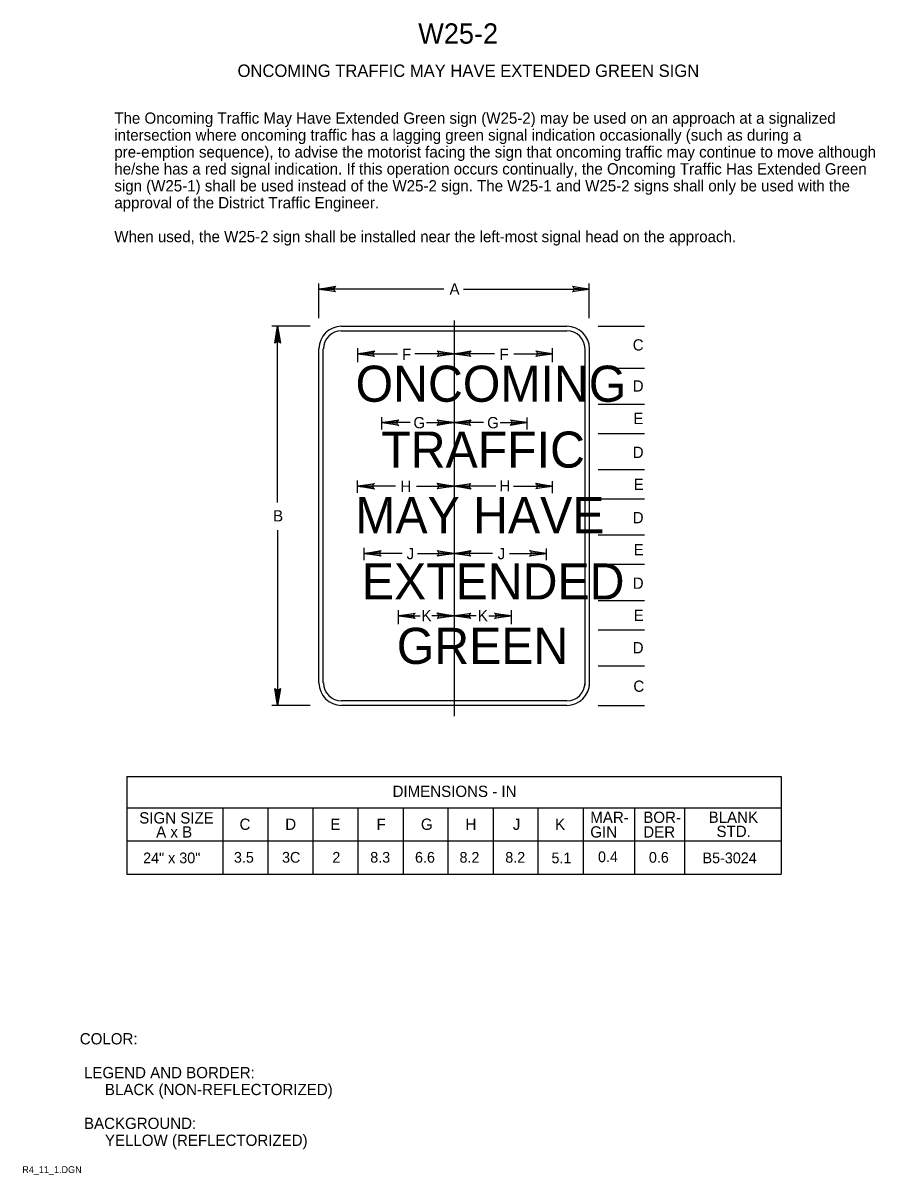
# Model space of a CAD drawing. Extents: x 0.013 to 0.201, y 0.004 to 0.259.
import ezdxf

# ---------------------------------------------------------------- set-up
doc = ezdxf.new("R2010")
doc.units = 0
for name, color, linetype in [('1', 7, 'Continuous'), ('11', 7, 'Continuous'), ('12', 7, 'Continuous'), ('2', 7, 'Continuous'), ('3', 7, 'Continuous')]:
    doc.layers.add(name, color=color, linetype=linetype)

# ---------------------------------------------------------------- blocks, each defined once
blk = doc.blocks.new('RARROW')
at = {"layer": '3'}
for p, q in [((-2.156, 0.285), (-2.2665, 0.384625)), ((-2.2665, 0.384625), (0, 0)), ((0, 0), (-2.2665, -0.379125)), ((-2.156, 0.285), (-2.075625, 0.12075)), ((0, 0), (-2.156, 0.285)), ((-2.14975, -0.2705), (0, 0)), ((-2.075625, 0.12075), (0, 0)), ((0, 0), (-2.074, -0.108)), ((-2.2665, -0.379125), (-2.14975, -0.2705)), ((-2.074, -0.108), (-2.14975, -0.2705))]:
    blk.add_line(p, q, dxfattribs=at)

msp = doc.modelspace()

# ---------------------------------------------------------------- linework, layer by layer
at = {"layer": '11'}
for p, q in [((0.08313, 0.192), (0.13312, 0.192)), ((0.07812, 0.113), (0.07812, 0.187)), ((0.13812, 0.187), (0.13812, 0.11235)), ((0.13312, 0.108), (0.08313, 0.108))]:
    msp.add_line(p, q, dxfattribs=at)
for centre, start, end in [((0.08317, 0.18699), 90, 180), ((0.13317, 0.18699), 0, 90), ((0.08317, 0.113), 180, 270), ((0.13317, 0.113), 270, 0)]:
    msp.add_arc(centre, 0.005, start, end, dxfattribs=at)
at = {"layer": '3'}
for p, q in [((0.07812, 0.19376), (0.07812, 0.2015)), ((0.10587, 0.20025), (0.07812, 0.20025)), ((0.11025, 0.20025), (0.13812, 0.20025)), ((0.13812, 0.19376), (0.13812, 0.2015)), ((0.07625, 0.192), (0.06775, 0.192)), ((0.069, 0.15293), (0.069, 0.192)), ((0.10812, 0.19325), (0.10812, 0.10562)), ((0.14012, 0.192), (0.15038, 0.192)), ((0.08313, 0.191), (0.13312, 0.191)), ((0.07912, 0.113), (0.07912, 0.187)), ((0.08676, 0.18405), (0.08676, 0.18716)), ((0.10812, 0.18729), (0.10812, 0.18466)), ((0.10812, 0.18591), (0.11188, 0.18653)), ((0.11168, 0.18635), (0.10812, 0.18591)), ((0.11156, 0.18609), (0.11168, 0.18635)), ((0.11188, 0.18653), (0.11168, 0.18635)), ((0.12642, 0.18638), (0.12624, 0.18654)), ((0.12624, 0.18654), (0.12999, 0.18591)), ((0.12642, 0.18638), (0.12656, 0.18611)), ((0.12999, 0.18591), (0.12642, 0.18638)), ((0.12999, 0.18405), (0.12999, 0.18716)), ((0.13712, 0.187), (0.13712, 0.11242)), ((0.08681, 0.18591), (0.09557, 0.18591)), ((0.10877, 0.18591), (0.09946, 0.18591)), ((0.10812, 0.18591), (0.11156, 0.18609)), ((0.11313, 0.18591), (0.10812, 0.18591)), ((0.11156, 0.18571), (0.10812, 0.18591)), ((0.10812, 0.18591), (0.11169, 0.18544)), ((0.11188, 0.18528), (0.10812, 0.18591)), ((0.11712, 0.18591), (0.10812, 0.18591)), ((0.11169, 0.18544), (0.11156, 0.18571)), ((0.11169, 0.18544), (0.11188, 0.18528)), ((0.12136, 0.18591), (0.12999, 0.18591)), ((0.12999, 0.18591), (0.12624, 0.18529)), ((0.12624, 0.18529), (0.12643, 0.18547)), ((0.12643, 0.18547), (0.12999, 0.18591)), ((0.12656, 0.18573), (0.12643, 0.18547)), ((0.12656, 0.18611), (0.12999, 0.18591)), ((0.12999, 0.18591), (0.12656, 0.18573)), ((0.14012, 0.18275), (0.15038, 0.18275)), ((0.14012, 0.17475), (0.15038, 0.17475)), ((0.0921, 0.16914), (0.0921, 0.17189)), ((0.10812, 0.17264), (0.10812, 0.16939)), ((0.12437, 0.16912), (0.12437, 0.17175)), ((0.0984, 0.17064), (0.09253, 0.17064)), ((0.10201, 0.17064), (0.10812, 0.17064)), ((0.11467, 0.17064), (0.10867, 0.17064)), ((0.11837, 0.17064), (0.12418, 0.17064)), ((0.14012, 0.16825), (0.15038, 0.16825)), ((0.14012, 0.16025), (0.15038, 0.16025)), ((0.08672, 0.15507), (0.08672, 0.15782)), ((0.09514, 0.15657), (0.08715, 0.15657)), ((0.09978, 0.15657), (0.10812, 0.15657)), ((0.10812, 0.15745), (0.10812, 0.15482)), ((0.11741, 0.15657), (0.10892, 0.15657)), ((0.12133, 0.15657), (0.12979, 0.15657)), ((0.12998, 0.15505), (0.12998, 0.15768)), ((0.14012, 0.15375), (0.15038, 0.15375)), ((0.069, 0.14685), (0.069, 0.108)), ((0.14012, 0.14575), (0.15038, 0.14575)), ((0.10812, 0.14362), (0.10812, 0.14037)), ((0.08822, 0.14018), (0.08822, 0.14293)), ((0.09664, 0.14168), (0.08865, 0.14168)), ((0.10003, 0.14168), (0.10812, 0.14168)), ((0.11665, 0.14168), (0.10867, 0.14168)), ((0.12039, 0.14168), (0.12842, 0.14168)), ((0.12861, 0.14016), (0.12861, 0.14278)), ((0.14012, 0.13925), (0.15038, 0.13925)), ((0.14012, 0.13125), (0.15038, 0.13125)), ((0.09579, 0.12597), (0.09579, 0.12909)), ((0.09579, 0.12784), (0.10059, 0.12784)), ((0.10877, 0.12784), (0.10318, 0.12784)), ((0.10812, 0.12921), (0.10812, 0.12659)), ((0.10812, 0.12784), (0.11188, 0.12846)), ((0.11168, 0.12828), (0.10812, 0.12784)), ((0.10812, 0.12784), (0.11156, 0.12801)), ((0.11156, 0.12764), (0.10812, 0.12784)), ((0.10812, 0.12784), (0.11169, 0.12737)), ((0.11188, 0.12721), (0.10812, 0.12784)), ((0.11279, 0.12784), (0.10812, 0.12784)), ((0.11307, 0.12784), (0.10812, 0.12784)), ((0.11156, 0.12801), (0.11168, 0.12828)), ((0.11169, 0.12737), (0.11156, 0.12764)), ((0.11188, 0.12846), (0.11168, 0.12828)), ((0.11586, 0.12784), (0.12085, 0.12784)), ((0.11729, 0.1283), (0.1171, 0.12846)), ((0.1171, 0.12846), (0.12085, 0.12784)), ((0.12085, 0.12784), (0.1171, 0.12721)), ((0.11729, 0.1283), (0.11742, 0.12803)), ((0.12085, 0.12784), (0.11729, 0.1283)), ((0.1173, 0.12739), (0.12085, 0.12784)), ((0.11742, 0.12766), (0.1173, 0.12739)), ((0.11742, 0.12803), (0.12085, 0.12784)), ((0.12085, 0.12784), (0.11742, 0.12766)), ((0.12085, 0.12597), (0.12085, 0.12909)), ((0.11169, 0.12737), (0.11188, 0.12721)), ((0.1171, 0.12721), (0.1173, 0.12739)), ((0.14012, 0.12475), (0.15038, 0.12475)), ((0.14012, 0.11675), (0.15038, 0.11675)), ((0.07625, 0.108), (0.06775, 0.108)), ((0.13312, 0.109), (0.08313, 0.109)), ((0.14012, 0.108), (0.15038, 0.108)), ((0.03556, 0.0922), (0.03556, 0.07057)), ((0.03556, 0.0922), (0.18069, 0.0922)), ((0.18069, 0.0922), (0.18069, 0.07057)), ((0.03556, 0.08532), (0.15671, 0.08532)), ((0.05686, 0.08532), (0.05686, 0.07057)), ((0.06681, 0.08532), (0.06681, 0.07057)), ((0.07681, 0.08532), (0.07681, 0.07057)), ((0.08681, 0.08532), (0.08681, 0.07057)), ((0.09681, 0.08532), (0.09681, 0.07057)), ((0.10677, 0.08532), (0.10677, 0.07057)), ((0.1168, 0.08532), (0.1168, 0.07057)), ((0.12672, 0.08532), (0.12672, 0.07057)), ((0.13676, 0.08532), (0.13676, 0.07057)), ((0.14814, 0.08532), (0.14814, 0.07057)), ((0.15671, 0.08532), (0.18069, 0.08532)), ((0.15926, 0.08532), (0.15926, 0.07057)), ((0.03556, 0.07795), (0.15671, 0.07795)), ((0.15671, 0.07795), (0.18069, 0.07795)), ((0.03556, 0.07057), (0.15671, 0.07057)), ((0.15671, 0.07057), (0.18069, 0.07057))]:
    msp.add_line(p, q, dxfattribs=at)
for centre, start, end in [((0.08317, 0.18699), 90, 180), ((0.13317, 0.18699), 0, 90), ((0.08317, 0.113), 180, 270), ((0.13317, 0.113), 270, 0)]:
    msp.add_arc(centre, 0.004, start, end, dxfattribs=at)

# ---------------------------------------------------------------- block references
at = {"layer": '3', "xscale": 0.0016545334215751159, "yscale": 0.0016366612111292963}
for p, rotation in [((0.07812, 0.20025), 180), ((0.069, 0.192), 90), ((0.08676, 0.18591), 180), ((0.0921, 0.17064), 180), ((0.10812, 0.17064), 180), ((0.08672, 0.15657), 180), ((0.10812, 0.15657), 180), ((0.08822, 0.14168), 180), ((0.10812, 0.14168), 180), ((0.09579, 0.12784), 180), ((0.069, 0.108), -90)]:
    msp.add_blockref('RARROW', p, dxfattribs=dict(at, rotation=rotation))
for p in [(0.13812, 0.20025), (0.10812, 0.18591), (0.10812, 0.17064), (0.12437, 0.17064), (0.10812, 0.15657), (0.12998, 0.15657), (0.10812, 0.14168), (0.12862, 0.14168), (0.10812, 0.12784)]:
    msp.add_blockref('RARROW', p, dxfattribs=at)

# ---------------------------------------------------------------- texts
at = {"layer": '1'}
for s, height, p in [('W25-2', 0.0045, (0.10018, 0.25462)), ('ONCOMING TRAFFIC MAY HAVE EXTENDED GREEN SIGN', 0.0027503, (0.06012, 0.24725)), ('COLOR:', 0.0025, (0.02513, 0.03287)), (' LEGEND AND BORDER:', 0.0024998, (0.02513, 0.02537)), ('      BLACK (NON-REFLECTORIZED)', 0.0024998, (0.02513, 0.02163)), (' BACKGROUND:', 0.0024998, (0.02513, 0.01413)), ('      YELLOW (REFLECTORIZED)', 0.0024998, (0.02513, 0.01038)), ('R4_11_1.DGN', 0.0015, (0.01238, 0.00438))]:
    msp.add_text(s, height=height, dxfattribs=at).set_placement(p)
at = {"layer": '12'}
for s, p in [('ONCOMING', (0.0863, 0.17527)), ('TRAFFIC', (0.09198, 0.16067)), ('MAY HAVE', (0.08621, 0.14615)), ('EXTENDED', (0.08768, 0.13146)), ('GREEN', (0.09543, 0.11718))]:
    msp.add_text(s, height=0.008, dxfattribs=at).set_placement(p)
at = {"layer": '2'}
for s, height, p in [('The Oncoming Traffic May Have Extended Green sign (W25-2) may be used on an approach at a signalized ', 0.00249975, (0.03279, 0.23688)), ('intersection where oncoming traffic has a lagging green signal indication occasionally (such as during a ', 0.00249975, (0.03279, 0.23313)), ('pre-emption sequence), to advise the motorist facing the sign that oncoming traffic may continue to move although ', 0.00249975, (0.03279, 0.22938)), ('he/she has a red signal indication. If this operation occurs continually, the Oncoming Traffic Has Extended Green ', 0.00249975, (0.03279, 0.22563)), ('sign (W25-1) shall be used instead of the W25-2 sign. The W25-1 and W25-2 signs shall only be used with the ', 0.00249975, (0.03279, 0.22188)), ('approval of the District Traffic Engineer.', 0.0024998, (0.03279, 0.21813)), ('When used, the W25-2 sign shall be installed near the left-most signal head on the approach.', 0.0024998, (0.03279, 0.21063))]:
    msp.add_text(s, height=height, dxfattribs=at).set_placement(p)
at = {"layer": '3'}
for s, height, p in [('A', 0.0025, (0.10712, 0.199)), ('C', 0.0025, (0.14775, 0.18662)), ('F', 0.0025, (0.09658, 0.18454)), ('F', 0.0025, (0.1182, 0.18454)), ('D', 0.0025, (0.14775, 0.17752)), ('G', 0.0025, (0.09912, 0.16939)), ('G', 0.0025, (0.11547, 0.16939)), ('E', 0.0025, (0.14788, 0.17032)), ('D', 0.0025, (0.14775, 0.16282)), ('H', 0.0025, (0.09623, 0.15527)), ('H', 0.0025, (0.1182, 0.15539)), ('E', 0.0025, (0.14795, 0.15571)), ('B', 0.0025, (0.068, 0.14875)), ('D', 0.0025, (0.14775, 0.14835)), ('E', 0.0025, (0.14795, 0.14124)), ('J', 0.0025, (0.09761, 0.14037)), ('J', 0.0025, (0.1178, 0.14037)), ('D', 0.0025, (0.14775, 0.13382)), ('K', 0.0025, (0.10091, 0.12665)), ('K', 0.0025, (0.1134, 0.12665)), ('E', 0.0025, (0.14795, 0.12671)), ('D', 0.0025, (0.14775, 0.11952)), ('C', 0.0025, (0.14789, 0.111)), ('DIMENSIONS - IN', 0.0024998, (0.09449, 0.0877)), ('SIGN SIZE', 0.0025, (0.03831, 0.08182)), ('MAR-', 0.0025, (0.13834, 0.08195)), ('BOR-', 0.0025, (0.15009, 0.08195)), ('BLANK', 0.0025, (0.16458, 0.08196)), ('C', 0.0025, (0.06056, 0.08041)), ('D', 0.0025, (0.07069, 0.08041)), ('E', 0.0025, (0.08069, 0.08041)), ('F', 0.0025, (0.09094, 0.08041)), ('G', 0.0025, (0.10078, 0.08041)), ('H', 0.0025, (0.11067, 0.08041)), ('J', 0.0025, (0.12116, 0.08041)), ('K', 0.0025, (0.13054, 0.08041)), ('A x B', 0.0025, (0.04206, 0.0787)), ('GIN', 0.0025, (0.13834, 0.0787)), ('DER', 0.0025, (0.15009, 0.0787)), ('STD.', 0.0025, (0.16633, 0.07883)), ('24" x 30"', 0.002375, (0.03918, 0.07301)), ('3.5', 0.002375, (0.05931, 0.07314)), ('3C', 0.002375, (0.06998, 0.07314)), ('2', 0.00238, (0.08114, 0.07314)), ('8.3', 0.002375, (0.08954, 0.07314)), ('6.6', 0.002375, (0.09947, 0.07314)), ('8.2', 0.002375, (0.10934, 0.07313)), ('8.2', 0.002375, (0.11948, 0.07313)), ('5.1', 0.002375, (0.12974, 0.07301)), ('0.4', 0.002375, (0.14005, 0.07326)), ('0.6', 0.002375, (0.15134, 0.07313)), ('B5-3024', 0.002375, (0.16324, 0.07301))]:
    msp.add_text(s, height=height, dxfattribs=at).set_placement(p)

doc.saveas('drawing.dxf')
